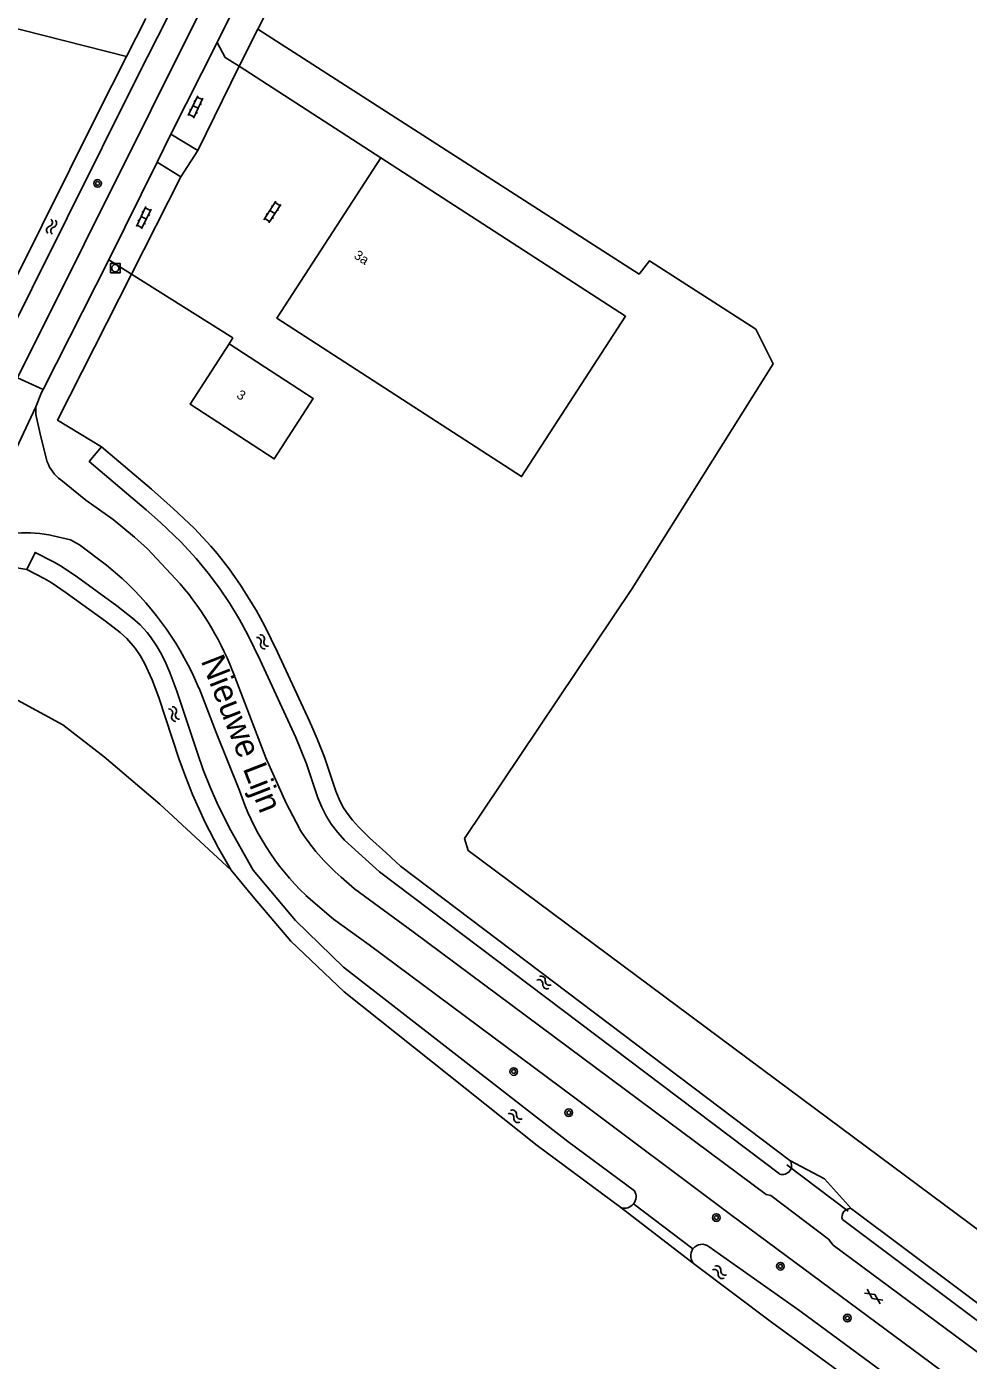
# Model space of a CAD drawing. Extents: x 124000 to 129000, y 395500 to 397503.
# Drawn here: x 126672.1 to 126770.6, y 396448.7 to 396588.2 of the extents above; entities that cross this region are included whole.
import ezdxf

# ---------------------------------------------------------------- set-up
doc = ezdxf.new("R2010")
doc.units = 0
for name, color, linetype in [('gg-anno-huisnummerreeks BGT', 7, 'Continuous'), ('gg-anno-openbare ruimte label', 7, 'Continuous'), ('gg-bbg-hoofdgebouw', 7, 'Continuous'), ('gg-knt-bronhoudergrens', 7, 'Continuous'), ('gg-knt-verharding', 7, 'Continuous'), ('gg-kntw-bovenkant insteek waterloop', 7, 'Continuous'), ('gg-kwrk-duiker nz buis', 7, 'Continuous'), ('gt-grn-groengrens', 7, 'Continuous'), ('gt-grn-vlakafsluiter', 7, 'Continuous'), ('gt-grn-weggrens', 7, 'Continuous'), ('gt-symb-boom', 7, 'Continuous'), ('gt-symb-gesloten verharding', 7, 'Continuous'), ('gt-symb-klinker verharding', 7, 'Continuous'), ('gt-symb-rioolschacht', 7, 'Continuous'), ('gt-symb-watersymbool', 7, 'Continuous'), ('gx-grn-maaiveld', 7, 'Continuous')]:
    doc.layers.add(name, color=color, linetype=linetype)

# ---------------------------------------------------------------- blocks, each defined once
blk = doc.blocks.new('gt0-GESVH1')
at = {"layer": 'gt-symb-gesloten verharding'}
for p, q in [((-0.99, -0.26), (0.01, 0.24)), ((0.01, -0.26), (-0.99, 0.24)), ((0.01, 0.24), (1.01, -0.26)), ((1.01, 0.24), (0.01, -0.26))]:
    blk.add_line(p, q, dxfattribs=at)
blk = doc.blocks.new('gt0-BOOM')
at = {"layer": 'gt-symb-boom'}
for radius in [0.4, 0.2]:
    blk.add_circle((0, 0), radius, dxfattribs=at)
blk = doc.blocks.new('gt0-WA')
at = {"layer": 'gt-symb-watersymbool'}
for centre, start, end in [((-0.32, 0.02), 28.0725, 151.9275), ((0.43, 0.42), 208.0725, 331.9275), ((-0.32, -0.43), 28.0725, 151.9275), ((0.43, -0.03), 208.0725, 331.9275)]:
    blk.add_arc(centre, 0.425, start, end, dxfattribs=at)
blk = doc.blocks.new('gt0-KL1')
at = {"layer": 'gt-symb-klinker verharding'}
for p, q in [((-1.15, 0.3), (1.15, 0.3)), ((-1, -0.3), (-1, 0.3)), ((-0.5, 0.3), (-0.5, 0.45)), ((0, -0.3), (0, 0.3)), ((0.5, 0.3), (0.5, 0.45)), ((1, -0.3), (1, 0.3)), ((-1.15, -0.3), (1.15, -0.3)), ((-0.5, -0.45), (-0.5, -0.3)), ((0.5, -0.45), (0.5, -0.3))]:
    blk.add_line(p, q, dxfattribs=at)
blk = doc.blocks.new('gt0-RS')
at = {"layer": 'gt-symb-rioolschacht'}
blk.add_lwpolyline([(-0.5, -0.5), (0.5, -0.5), (0.5, 0.5), (-0.5, 0.5)], close=True, dxfattribs=at)
blk.add_circle((0, 0), 0.375, dxfattribs=at)

msp = doc.modelspace()

# ---------------------------------------------------------------- linework, layer by layer
at = {"layer": 'gg-bbg-hoofdgebouw'}
for points in [[(126709.16, 396574.47), (126698.28, 396557.7), (126723.87, 396541.16), (126734.75, 396557.92), (126709.16, 396574.47)], [(126693.28, 396555.04), (126689.2, 396548.74), (126698, 396543), (126702.08, 396549.3), (126693.28, 396555.04)]]:
    msp.add_lwpolyline(points, dxfattribs=at)
at = {"layer": 'gg-knt-bronhoudergrens'}
msp.add_line((126734.25, 396464.71), (126742, 396458.75), dxfattribs=at)
for points in [[(126696.28, 396587.95), (126736.16, 396562.32), (126737.25, 396563.7), (126748.37, 396556.55)], [(126748.37, 396556.55), (126750.19, 396552.95), (126735.43, 396529.45), (126717.89, 396503.3)], [(126717.89, 396503.3), (126718.29, 396502.05), (126751.95, 396477.04), (126786.89, 396451.08), (126788.41, 396450.68), (126792.98, 396457.67), (126850.07, 396542.31)]]:
    msp.add_lwpolyline(points, dxfattribs=at)
at = {"layer": 'gg-knt-verharding'}
for p, q in [((126692.03, 396586.53), (126687.19, 396576.94)), ((126694.32, 396584.05), (126709.16, 396574.47)), ((126685.75, 396574.04), (126687.19, 396576.94)), ((126687.19, 396576.94), (126689.99, 396575.25)), ((126689.99, 396575.25), (126688.21, 396572.48)), ((126685.75, 396574.04), (126680.69, 396563.83)), ((126688.21, 396572.48), (126685.75, 396574.04)), ((126680.69, 396563.83), (126673.83, 396550.26)), ((126680.69, 396563.83), (126683.07, 396562.33))]:
    msp.add_line(p, q, dxfattribs=at)
for points in [[(126729.9, 396662.87), (126720.52, 396644.04), (126692.03, 396586.53)], [(126671.15, 396551.49), (126699.07, 396607.48), (126699.07, 396607.87)], [(126692.03, 396586.53), (126692.88, 396584.98), (126694.32, 396584.05)], [(126683.07, 396562.33), (126693.66, 396555.65), (126693.28, 396555.04)], [(126673.83, 396550.26), (126673.66, 396549.93), (126673.05, 396548.44)], [(126673.05, 396548.44), (126673.07, 396547.66), (126673.58, 396545.3), (126674.26, 396542.69)], [(126688.17, 396529.94), (126684.74, 396533.59), (126683.39, 396534.82), (126681.16, 396536.65), (126678.28, 396538.68), (126675.66, 396540.8)], [(126674.41, 396535.05), (126676.67, 396534.53), (126677.61, 396534.03), (126680.45, 396531.88), (126682.09, 396530.49)], [(126693.86, 396520.23), (126697.11, 396511.75), (126699.23, 396507.02), (126700.64, 396504.34)], [(126694.36, 396508.32), (126691.93, 396514.41), (126690.13, 396519.02)], [(126827.7, 396408.05), (126821.37, 396412.59), (126798.78, 396429.44), (126756.47, 396460.8), (126755.97, 396461.41), (126749.95, 396465.98), (126749.47, 396466.07), (126712.54, 396493.55), (126706.39, 396498.06), (126705.01, 396499.26)], [(126829.14, 396402.74), (126825.56, 396404.92), (126819.84, 396408.96), (126796.57, 396426.3), (126795.8, 396426.73), (126790.05, 396430.99), (126789.32, 396431.67), (126766.74, 396448.46), (126745.74, 396464.01), (126729.45, 396476.18), (126707.93, 396492.2), (126704.19, 396494.88), (126701.29, 396497.36)]]:
    msp.add_lwpolyline(points, dxfattribs=at)
for centre, radius, start, end in [((126678.13, 396544.1), 4.12, 199.9924, 233.2418), ((126672.03, 396522.49), 12.78, 79.2645, 96.4823), ((126659.38, 396506.05), 33.37, 22.8759, 47.1068), ((126663.27, 396508.81), 32.66, 20.4795, 40.3142), ((126720.02, 396516.89), 27.05, 198.4716, 226.1886), ((126720.16, 396516.7), 23.11, 212.3464, 229.0268)]:
    msp.add_arc(centre, radius, start, end, dxfattribs=at)
at = {"layer": 'gg-kntw-bovenkant insteek waterloop'}
for p, q in [((126685.8, 396587.11), (126697.33, 396610.25)), ((126685.8, 396587.11), (126683.7, 396582.97)), ((126683.7, 396582.97), (126660.74, 396536.94))]:
    msp.add_line(p, q, dxfattribs=at)
for points in [[(126659.34, 396538.62), (126679.49, 396579.02), (126682.54, 396585.06)], [(126704.65, 396503.94), (126703.98, 396504.79), (126703.45, 396505.62), (126702.96, 396506.59), (126702.56, 396507.57), (126701.36, 396511.13), (126700.25, 396513.86), (126696.53, 396521.94), (126695.23, 396524.6), (126694.36, 396526.2), (126693.35, 396527.88), (126692.26, 396529.5), (126691.09, 396531.07), (126689.84, 396532.57), (126688.22, 396534.32), (126686.09, 396536.36), (126684.61, 396537.68), (126678.65, 396542.74), (126679.93, 396544.28)], [(126679.93, 396544.28), (126685.16, 396539.84), (126687.43, 396537.83), (126689.64, 396535.72), (126691.35, 396533.88), (126692.02, 396533.1), (126693.29, 396531.49), (126694.47, 396529.81), (126696.1, 396527.19), (126697.01, 396525.52), (126698.34, 396522.79), (126701.67, 396515.59), (126702.48, 396513.73), (126703.24, 396511.82), (126704.43, 396508.27), (126704.78, 396507.42), (126705.19, 396506.62), (126705.62, 396505.95), (126706.18, 396505.22), (126706.82, 396504.52), (126707.96, 396503.39), (126709.67, 396501.83)], [(126750.86, 396468.23), (126709.02, 396499.83), (126705.36, 396503.15), (126704.65, 396503.94)], [(126751.95, 396469.65), (126711.21, 396500.42), (126709.67, 396501.83)], [(126695.8, 396500), (126700.23, 396494.75), (126705.25, 396489.84), (126728.72, 396471.64), (126735.68, 396466.48)], [(126831.05, 396411.72), (126817.62, 396420.48), (126781.68, 396447.15), (126758.4, 396464.6)], [(126757.44, 396463.47), (126811.55, 396422.92), (126829.64, 396410.04)], [(126743.51, 396460.62), (126752.98, 396453.93), (126788.9, 396427.47), (126787.38, 396425.4)], [(126787.38, 396425.4), (126765.9, 396441.17), (126750.01, 396452.74), (126742, 396458.75)]]:
    msp.add_lwpolyline(points, dxfattribs=at)
for centre, radius, start, end in [((126751.17, 396469.12), 0.946, 250.9854, 33.6124), ((126734.63, 396465.86), 1.22, 321.1801, 30.341), ((126734.63, 396465.86), 1.21, 251.9332, 321.1788), ((126758.24, 396463.76), 0.853, 79.332, 200.3357), ((126742.76, 396459.68), 1.2, 142.8664, 230.5895), ((126742.76, 396459.68), 1.2, 51.5258, 142.8567)]:
    msp.add_arc(centre, radius, start, end, dxfattribs=at)
at = {"layer": 'gg-kwrk-duiker nz buis'}
for p, q in [((126751.63, 396469.18), (126758.05, 396464.34)), ((126735.58, 396465.1), (126741.8, 396460.4))]:
    msp.add_line(p, q, dxfattribs=at)
at = {"layer": 'gt-grn-groengrens'}
msp.add_line((126694.32, 396584.05), (126696.28, 396587.95), dxfattribs=at)
for points in [[(126696.28, 396587.95), (126731.96, 396659.06), (126768.12, 396731.4)], [(126683.07, 396562.33), (126675.34, 396547.05), (126679.93, 396544.28)], [(126672.12, 396531.42), (126667.51, 396532.21), (126662.43, 396521.52)], [(126751.95, 396469.65), (126755.58, 396467.73), (126758.4, 396464.6)]]:
    msp.add_lwpolyline(points, dxfattribs=at)
at = {"layer": 'gt-grn-vlakafsluiter'}
for p, q in [((126689.99, 396575.25), (126694.32, 396584.05)), ((126688.21, 396572.48), (126683.07, 396562.33))]:
    msp.add_line(p, q, dxfattribs=at)
at = {"layer": 'gt-grn-weggrens'}
for p, q in [((126671.15, 396551.49), (126673.83, 396550.26)), ((126673.05, 396548.44), (126666.36, 396534.22))]:
    msp.add_line(p, q, dxfattribs=at)
at = {"layer": 'gx-grn-maaiveld'}
for q in [(126684.56, 396589.05), (126682.54, 396585.06)]:
    msp.add_line((126682.55, 396585.06), q, dxfattribs=at)
for points in [[(126682.55, 396585.06), (126647.76, 396593.93), (126637.07, 396596.05), (126632.63, 396597.74), (126620.67, 396602.19), (126608.92, 396607.05), (126590.62, 396570.06)], [(126672.12, 396531.42), (126672.98, 396533.23), (126674.91, 396532.24), (126675.7, 396531.77), (126677.4, 396530.62), (126681.53, 396527.64), (126683.18, 396526.36), (126683.97, 396525.64), (126684.69, 396524.86), (126685.06, 396524.4), (126685.66, 396523.52), (126686.19, 396522.59), (126686.66, 396521.64), (126687.07, 396520.66), (126687.8, 396518.7), (126689.92, 396512.33), (126690.58, 396510.49), (126691.29, 396508.68), (126692.14, 396506.77), (126693.47, 396504.14), (126695.8, 396500)], [(126693.49, 396500), (126692.18, 396502.31), (126690.78, 396505), (126689.45, 396507.91), (126688.7, 396509.79), (126688.03, 396511.68), (126685.91, 396518.04), (126685.22, 396519.91), (126684.42, 396521.66), (126683.96, 396522.46), (126683.45, 396523.21), (126682.56, 396524.22), (126681.88, 396524.84), (126680.35, 396526.02), (126676.24, 396528.99), (126674.65, 396530.07), (126673.93, 396530.49), (126672.12, 396531.42)], [(126662.43, 396521.52), (126670.37, 396518.19), (126675.87, 396515.18), (126680.22, 396511.85), (126686.02, 396506.89), (126693.49, 396500)], [(126693.49, 396500), (126695.81, 396497.2), (126699.73, 396492.56)], [(126734.25, 396464.71), (126725.5, 396471.22), (126705.33, 396487.29), (126699.73, 396492.56)]]:
    msp.add_lwpolyline(points, dxfattribs=at)

# ---------------------------------------------------------------- block references
at = {"layer": 'gt-symb-boom'}
for p in [(126679.52, 396571.81), (126723.05, 396478.94), (126728.81, 396474.64), (126744.25, 396463.67), (126750.95, 396458.58), (126757.96, 396453.17)]:
    msp.add_blockref('gt0-BOOM', p, dxfattribs=at)
at = {"layer": 'gt-symb-gesloten verharding', "rotation": -34.73862528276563}
msp.add_blockref('gt0-GESVH1', (126760.7, 396455.43), dxfattribs=at)
at = {"layer": 'gt-symb-klinker verharding'}
for p, rotation in [((126689.77, 396579.8), 64.35692916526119), ((126684.35, 396568.21), 64.40857585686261), ((126697.8, 396568.81), -122.95900987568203)]:
    msp.add_blockref('gt0-KL1', p, dxfattribs=dict(at, rotation=rotation))
at = {"layer": 'gt-symb-rioolschacht'}
msp.add_blockref('gt0-RS', (126681.37, 396562.94), dxfattribs=at)
at = {"layer": 'gt-symb-watersymbool'}
for p, rotation in [((126674.69, 396567.23), 77.99329169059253), ((126696.74, 396523.92), -52.84362584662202), ((126687.49, 396516.37), -60.205382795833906), ((126726.27, 396488.22), 144.68878656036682), ((126723.24, 396474.23), 144.68878656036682), ((126744.62, 396457.92), 143.74924417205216)]:
    msp.add_blockref('gt0-WA', p, dxfattribs=dict(at, rotation=rotation))

# ---------------------------------------------------------------- texts
at = {"layer": 'gg-anno-huisnummerreeks BGT'}
for s, rotation, p in [('3a', 327, (126706.25, 396564.06)), ('3', 327.1, (126693.97, 396549.46))]:
    msp.add_text(s, height=1, rotation=rotation, dxfattribs=at).set_placement(p)
at = {"layer": 'gg-anno-openbare ruimte label'}
msp.add_text('Nieuwe Lijn', height=2.5, rotation=291.3, dxfattribs=at).set_placement((126690.3, 396521.9))

doc.saveas('drawing.dxf')
